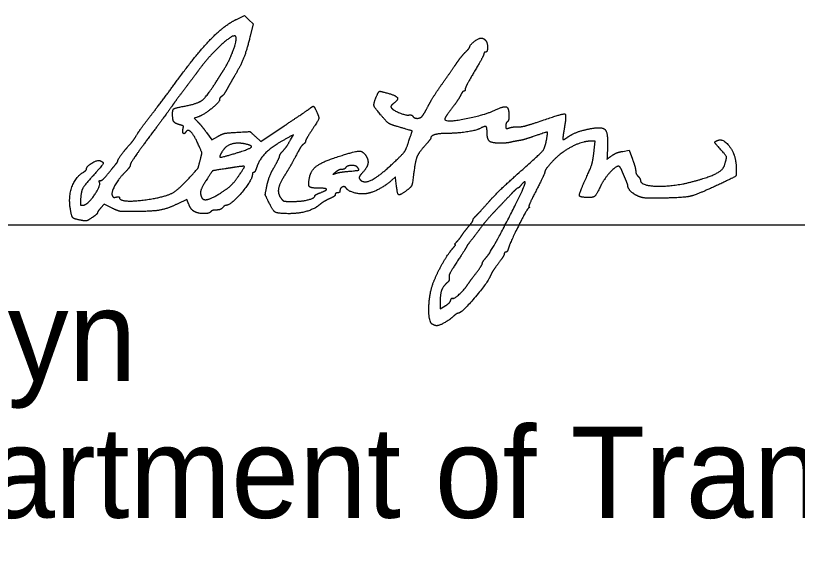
# Model space of a CAD drawing. Extents: x 0 to 44, y -23.8 to 22.
# Drawn here: x 25.658 to 26.858, y 6.74 to 7.554 of the extents above; entities that cross this region are included whole.
import ezdxf

# ---------------------------------------------------------------- set-up
doc = ezdxf.new("R2010")
doc.units = 0
for name, color, linetype in [('Default', 7, 'Continuous'), ('SH_Data', 7, 'Continuous'), ('SH_Text', 7, 'Continuous')]:
    doc.layers.add(name, color=color, linetype=linetype)

msp = doc.modelspace()

# ---------------------------------------------------------------- linework, layer by layer
at = {"layer": 'Default'}
for points in [[(25.9971, 7.5478), (26.0097, 7.5537), (26.0161, 7.5473), (26.0225, 7.5409), (26.0181, 7.5222)], [(25.9372, 7.3978), (25.9322, 7.3963), (25.9373, 7.3911)], [(26.0261, 7.3681), (26.0343, 7.3605), (26.0705, 7.3846)], [(25.951, 7.3744), (25.9595, 7.3629), (25.9683, 7.3681)], [(26.08, 7.3629), (26.0845, 7.3708), (26.079, 7.3679)], [(26.5459, 7.347), (26.5474, 7.3608), (26.5395, 7.3608)], [(26.5897, 7.3453), (26.5994, 7.3469), (26.6045, 7.3333)], [(26.2418, 7.2992), (26.2411, 7.306), (26.2353, 7.3009)], [(25.9242, 7.2636), (25.9208, 7.2716), (25.907, 7.2648)], [(25.8055, 7.2585), (25.794, 7.2643), (25.789, 7.2585)], [(26.3095, 7.1131), (26.3095, 7.1037), (26.3171, 7.108)]]:
    msp.add_lwpolyline(points, dxfattribs=at)
for points in [[(25.9075, 7.4559), (25.9372, 7.4965), (25.979, 7.5394), (25.9971, 7.5478)], [(25.9957, 7.522), (25.992, 7.5257), (25.9535, 7.4899), (25.9381, 7.4686)], [(25.9774, 7.47), (25.9868, 7.4848), (25.9988, 7.5189), (25.9957, 7.522)], [(26.0181, 7.5222), (26.0131, 7.5011), (26.0039, 7.4775), (25.9945, 7.4616)], [(26.3551, 7.5059), (26.3551, 7.5087), (26.3683, 7.519), (26.3721, 7.5191)], [(26.3721, 7.5191), (26.3741, 7.5191), (26.3771, 7.5179), (26.3787, 7.5163)], [(26.3787, 7.5163), (26.3821, 7.5128), (26.3825, 7.4976), (26.3791, 7.4976)], [(26.3348, 7.4806), (26.3387, 7.4864), (26.3449, 7.4941), (26.3485, 7.4978)], [(26.3485, 7.4978), (26.3522, 7.5014), (26.3551, 7.5051), (26.3551, 7.5059)], [(26.3767, 7.495), (26.3767, 7.4937), (26.3703, 7.4816), (26.3623, 7.4682)], [(26.3791, 7.4976), (26.3778, 7.4976), (26.3767, 7.4964), (26.3767, 7.495)], [(26.3131, 7.4496), (26.3211, 7.4608), (26.3308, 7.4747), (26.3348, 7.4806)], [(25.9381, 7.4686), (25.9345, 7.4637), (25.9251, 7.451), (25.9171, 7.4405)], [(25.9668, 7.4533), (25.9701, 7.4585), (25.9748, 7.466), (25.9774, 7.47)], [(25.9945, 7.4616), (25.9909, 7.4556), (25.9857, 7.4464), (25.9829, 7.4412)], [(26.3623, 7.4682), (26.3544, 7.4548), (26.3479, 7.4424), (26.3479, 7.4407)], [(25.8674, 7.4025), (25.8763, 7.4138), (25.8943, 7.4379), (25.9075, 7.4559)], [(25.917, 7.4146), (25.9376, 7.4184), (25.9517, 7.4293), (25.9668, 7.4533)], [(26.2918, 7.416), (26.2956, 7.4232), (26.3052, 7.4383), (26.3131, 7.4496)], [(25.9171, 7.4405), (25.9092, 7.43), (25.9011, 7.419), (25.8991, 7.4161)], [(25.9829, 7.4412), (25.98, 7.4359), (25.9762, 7.4307), (25.9744, 7.4296)], [(26.2111, 7.4278), (26.2148, 7.4369), (26.218, 7.4379), (26.2307, 7.4341)], [(26.3459, 7.4376), (26.3448, 7.4376), (26.3425, 7.4346), (26.3407, 7.431)], [(26.3479, 7.4407), (26.3479, 7.439), (26.347, 7.4376), (26.3459, 7.4376)], [(25.9711, 7.4242), (25.9711, 7.4205), (25.9454, 7.4004), (25.9372, 7.3978)], [(25.9744, 7.4296), (25.9726, 7.4286), (25.9711, 7.4261), (25.9711, 7.4242)], [(26.2209, 7.3984), (26.2094, 7.4114), (26.2071, 7.4182), (26.2111, 7.4278)], [(26.2307, 7.4341), (26.2427, 7.4306), (26.2455, 7.4244), (26.2379, 7.4186)], [(26.3407, 7.431), (26.3389, 7.4273), (26.3328, 7.4182), (26.3271, 7.4108)], [(25.8991, 7.4161), (25.8972, 7.4131), (25.8818, 7.3922), (25.865, 7.3695)], [(25.8991, 7.4025), (25.8991, 7.4094), (25.9033, 7.4121), (25.917, 7.4146)], [(26.0705, 7.3846), (26.0904, 7.3979), (26.108, 7.4098), (26.1096, 7.4111)], [(26.1096, 7.4111), (26.1142, 7.4149), (26.1165, 7.414), (26.1196, 7.4074)], [(26.2379, 7.4186), (26.2351, 7.4165), (26.2336, 7.4136), (26.2346, 7.4123)], [(26.2346, 7.4123), (26.2373, 7.4085), (26.2572, 7.4003), (26.2618, 7.4011)], [(26.2825, 7.3998), (26.2838, 7.4014), (26.2879, 7.4087), (26.2918, 7.416)], [(26.3943, 7.4089), (26.4073, 7.4151), (26.4151, 7.412), (26.4151, 7.4006)], [(25.8458, 7.3731), (25.8488, 7.3779), (25.8585, 7.3911), (25.8674, 7.4025)], [(25.9101, 7.3861), (25.903, 7.3879), (25.8991, 7.3936), (25.8991, 7.4025)], [(26.1196, 7.4074), (26.1239, 7.3978), (26.123, 7.3937), (26.1127, 7.3778)], [(26.2618, 7.4011), (26.2641, 7.4015), (26.2666, 7.4007), (26.2675, 7.3993)], [(26.2675, 7.3993), (26.2696, 7.3958), (26.2797, 7.3961), (26.2825, 7.3998)], [(26.3271, 7.4108), (26.3214, 7.4033), (26.3167, 7.396), (26.3167, 7.3947)], [(26.3167, 7.3947), (26.3167, 7.3894), (26.3764, 7.4004), (26.3943, 7.4089)], [(26.4151, 7.4006), (26.4151, 7.396), (26.4141, 7.3916), (26.4127, 7.3908)], [(26.4575, 7.3898), (26.4978, 7.4037), (26.5038, 7.4021), (26.4996, 7.3782)], [(25.9373, 7.3911), (25.9401, 7.3883), (25.9463, 7.3808), (25.951, 7.3744)], [(26.2443, 7.3832), (26.2336, 7.3864), (26.2287, 7.3895), (26.2209, 7.3984)], [(26.4127, 7.3908), (26.4114, 7.3899), (26.4103, 7.3871), (26.4103, 7.3845)], [(26.4287, 7.3828), (26.4328, 7.3826), (26.4458, 7.3858), (26.4575, 7.3898)], [(25.9152, 7.3798), (25.9161, 7.3834), (25.9149, 7.3849), (25.9101, 7.3861)], [(25.9195, 7.3751), (25.9171, 7.3712), (25.9139, 7.3747), (25.9152, 7.3798)], [(25.9383, 7.3565), (25.9322, 7.3702), (25.9224, 7.3798), (25.9195, 7.3751)], [(25.9976, 7.3746), (26.0179, 7.3757), (26.018, 7.3757), (26.0261, 7.3681)], [(26.1127, 7.3778), (26.1075, 7.3697), (26.1031, 7.3621), (26.1031, 7.361)], [(26.2611, 7.3595), (26.2668, 7.3763), (26.2664, 7.3769), (26.2443, 7.3832)], [(26.3701, 7.3801), (26.3645, 7.3771), (26.3343, 7.3728), (26.3194, 7.3728)], [(26.3815, 7.3754), (26.3815, 7.3827), (26.3779, 7.3843), (26.3701, 7.3801)], [(26.4009, 7.3578), (26.3885, 7.3578), (26.3815, 7.3641), (26.3815, 7.3754)], [(26.4103, 7.3845), (26.4103, 7.3805), (26.4114, 7.38), (26.4157, 7.3814)], [(26.4157, 7.3814), (26.4187, 7.3823), (26.4245, 7.383), (26.4287, 7.3828)], [(26.4728, 7.3632), (26.4749, 7.3747), (26.4731, 7.3751), (26.4521, 7.3679)], [(26.4996, 7.3782), (26.4983, 7.3706), (26.4976, 7.364), (26.498, 7.3635)], [(26.5056, 7.3674), (26.5128, 7.3724), (26.5311, 7.3787), (26.5447, 7.3809)], [(26.5447, 7.3809), (26.5594, 7.3832), (26.567, 7.3728), (26.5663, 7.3515)], [(25.8295, 7.3512), (25.8361, 7.3586), (25.8404, 7.3643), (25.8458, 7.3731)], [(25.865, 7.3695), (25.8482, 7.3469), (25.8344, 7.3267), (25.8343, 7.3248)], [(25.9683, 7.3681), (25.9749, 7.372), (25.9824, 7.3737), (25.9976, 7.3746)], [(26.079, 7.3679), (26.0556, 7.3553), (26.0328, 7.3347), (26.0287, 7.3222)], [(26.0672, 7.3447), (26.0727, 7.3507), (26.0752, 7.3543), (26.08, 7.3629)], [(26.2951, 7.3656), (26.2951, 7.3647), (26.2909, 7.3593), (26.2858, 7.3535)], [(26.3194, 7.3728), (26.3079, 7.3728), (26.2951, 7.369), (26.2951, 7.3656)], [(26.4279, 7.3102), (26.4634, 7.3418), (26.4703, 7.35), (26.4728, 7.3632)], [(26.4521, 7.3679), (26.4443, 7.3652), (26.4347, 7.3624), (26.4307, 7.3618)], [(26.498, 7.3635), (26.4985, 7.363), (26.5019, 7.3648), (26.5056, 7.3674)], [(26.7354, 7.3622), (26.744, 7.3655), (26.7625, 7.3406), (26.7635, 7.3243)], [(25.8151, 7.3308), (25.8151, 7.3324), (25.8243, 7.3454), (25.8295, 7.3512)], [(25.9416, 7.332), (25.9442, 7.3418), (25.9439, 7.344), (25.9383, 7.3565)], [(26.0093, 7.3568), (25.9985, 7.359), (25.9811, 7.3539), (25.9768, 7.3473)], [(25.9987, 7.3433), (26.018, 7.3492), (26.022, 7.3543), (26.0093, 7.3568)], [(26.0996, 7.356), (26.0976, 7.3544), (26.0945, 7.3502), (26.0927, 7.3467)], [(26.1031, 7.361), (26.1031, 7.3599), (26.1015, 7.3576), (26.0996, 7.356)], [(26.2428, 7.3322), (26.2533, 7.3422), (26.2574, 7.3484), (26.2611, 7.3595)], [(26.2858, 7.3535), (26.2773, 7.3441), (26.2716, 7.3315), (26.27, 7.3188)], [(26.4175, 7.3592), (26.4142, 7.3584), (26.4067, 7.3578), (26.4009, 7.3578)], [(26.4307, 7.3618), (26.4268, 7.3611), (26.4208, 7.36), (26.4175, 7.3592)], [(26.5395, 7.3608), (26.5269, 7.3608), (26.4931, 7.3423), (26.4809, 7.3288)], [(26.5663, 7.3515), (26.5656, 7.3331), (26.5654, 7.3334), (26.5732, 7.3389)], [(26.7363, 7.3521), (26.731, 7.3578), (26.7308, 7.3605), (26.7354, 7.3622)], [(26.7455, 7.323), (26.7494, 7.3348), (26.7479, 7.3397), (26.7363, 7.3521)], [(25.9768, 7.3473), (25.9698, 7.3366), (25.9743, 7.3358), (25.9987, 7.3433)], [(26.0633, 7.3377), (26.0635, 7.3395), (26.0653, 7.3426), (26.0672, 7.3447)], [(26.0927, 7.3467), (26.0846, 7.3313), (26.0768, 7.3175), (26.0707, 7.3078)], [(26.1465, 7.335), (26.1784, 7.3456), (26.1918, 7.346), (26.1968, 7.3366)], [(26.5312, 7.2991), (26.5403, 7.319), (26.5443, 7.3322), (26.5459, 7.347)], [(26.5732, 7.3389), (26.577, 7.3416), (26.5844, 7.3445), (26.5897, 7.3453)], [(25.7672, 7.3187), (25.7672, 7.3225), (25.784, 7.3325), (25.7878, 7.331)], [(25.7878, 7.331), (25.7937, 7.3287), (25.7915, 7.3238), (25.7771, 7.3079)], [(25.8127, 7.3265), (25.8141, 7.328), (25.8151, 7.33), (25.8151, 7.3308)], [(25.9219, 7.3015), (25.938, 7.319), (25.9383, 7.3196), (25.9416, 7.332)], [(26.0548, 7.3206), (26.0592, 7.3283), (26.063, 7.336), (26.0633, 7.3377)], [(26.1089, 7.3039), (26.111, 7.3152), (26.1272, 7.3286), (26.1465, 7.335)], [(26.1858, 7.3033), (26.1912, 7.2947), (26.2179, 7.3082), (26.2428, 7.3322)], [(26.1968, 7.3366), (26.2001, 7.3305), (26.1967, 7.3191), (26.1892, 7.3112)], [(26.4809, 7.3288), (26.4751, 7.3223), (26.4703, 7.3157), (26.4703, 7.3142)], [(26.6045, 7.3333), (26.6073, 7.3259), (26.6095, 7.3177), (26.6095, 7.3152)], [(25.7625, 7.3134), (25.765, 7.315), (25.7672, 7.3174), (25.7672, 7.3187)], [(25.8006, 7.3116), (25.806, 7.3182), (25.8114, 7.3249), (25.8127, 7.3265)], [(25.8343, 7.3248), (25.8343, 7.3228), (25.8309, 7.318), (25.827, 7.314)], [(25.9795, 7.3185), (25.9618, 7.3159), (25.9597, 7.3148), (25.9525, 7.3036)], [(25.9969, 7.3212), (25.9913, 7.3203), (25.9835, 7.3191), (25.9795, 7.3185)], [(26.0019, 7.3095), (26.0098, 7.3209), (26.0088, 7.323), (25.9969, 7.3212)], [(26.0287, 7.3222), (26.027, 7.317), (26.0247, 7.3128), (26.0236, 7.3128)], [(26.0439, 7.2928), (26.0455, 7.3005), (26.0504, 7.313), (26.0548, 7.3206)], [(26.1587, 7.3176), (26.1563, 7.3176), (26.1524, 7.3158), (26.1498, 7.3138)], [(26.1642, 7.3197), (26.1634, 7.3185), (26.161, 7.3176), (26.1587, 7.3176)], [(26.1827, 7.3208), (26.1799, 7.3241), (26.1664, 7.3234), (26.1642, 7.3197)], [(26.1667, 7.3144), (26.1835, 7.3159), (26.1859, 7.3169), (26.1827, 7.3208)], [(26.27, 7.3188), (26.2671, 7.2963), (26.2654, 7.2908), (26.2597, 7.2863)], [(26.5828, 7.3224), (26.5784, 7.3224), (26.5602, 7.3018), (26.5555, 7.2917)], [(26.5883, 7.3158), (26.5869, 7.3194), (26.5843, 7.3224), (26.5828, 7.3224)], [(26.5943, 7.3016), (26.5925, 7.3058), (26.5898, 7.3121), (26.5883, 7.3158)], [(26.6095, 7.3152), (26.6095, 7.3127), (26.6112, 7.3091), (26.6131, 7.3071)], [(26.6966, 7.2988), (26.7203, 7.305), (26.7432, 7.3164), (26.7455, 7.323)], [(26.7635, 7.3243), (26.7644, 7.309), (26.7617, 7.3059), (26.7383, 7.2949)], [(25.7423, 7.2571), (25.7393, 7.2756), (25.7501, 7.3057), (25.7625, 7.3134)], [(25.7771, 7.3079), (25.7634, 7.2928), (25.7585, 7.2826), (25.7579, 7.2688)], [(25.7883, 7.3003), (25.7897, 7.2999), (25.7953, 7.305), (25.8006, 7.3116)], [(25.827, 7.314), (25.8171, 7.3044), (25.8047, 7.2823), (25.8065, 7.2776)], [(25.9525, 7.3036), (25.9443, 7.2909), (25.9411, 7.2811), (25.9433, 7.2753)], [(25.9721, 7.2808), (25.9832, 7.2878), (25.9942, 7.2983), (26.0019, 7.3095)], [(26.0215, 7.3098), (26.0214, 7.3012), (25.9883, 7.2624), (25.9811, 7.2624)], [(26.0236, 7.3128), (26.0224, 7.3128), (26.0215, 7.3114), (26.0215, 7.3098)], [(26.0707, 7.3078), (26.0627, 7.2952), (26.0604, 7.28), (26.0655, 7.2732)], [(26.1225, 7.2888), (26.111, 7.2888), (26.1069, 7.2933), (26.1089, 7.3039)], [(26.1498, 7.3138), (26.1452, 7.31), (26.1452, 7.31), (26.1499, 7.3117)], [(26.1499, 7.3117), (26.1526, 7.3126), (26.1601, 7.3138), (26.1667, 7.3144)], [(26.1892, 7.3112), (26.1865, 7.3083), (26.185, 7.3048), (26.1858, 7.3033)], [(26.3839, 7.2675), (26.3911, 7.2759), (26.4109, 7.2951), (26.4279, 7.3102)], [(26.4703, 7.3142), (26.4703, 7.3126), (26.4644, 7.2998), (26.4571, 7.2856)], [(26.6131, 7.3071), (26.6151, 7.3051), (26.6167, 7.3024), (26.6167, 7.3011)], [(25.7627, 7.2628), (25.769, 7.2637), (25.7891, 7.2922), (25.7871, 7.2974)], [(25.7871, 7.2974), (25.7864, 7.2993), (25.7869, 7.3006), (25.7883, 7.3003)], [(25.8654, 7.2721), (25.8882, 7.2758), (25.9078, 7.286), (25.9219, 7.3015)], [(26.0459, 7.2688), (26.0414, 7.2779), (26.0412, 7.2801), (26.0439, 7.2928)], [(26.1654, 7.2889), (26.1634, 7.2922), (26.1559, 7.289), (26.1559, 7.2849)], [(26.2353, 7.3009), (26.2259, 7.2927), (26.2059, 7.2821), (26.1967, 7.2804)], [(26.2597, 7.2863), (26.248, 7.2771), (26.2436, 7.2802), (26.2418, 7.2992)], [(26.3813, 7.1837), (26.3889, 7.1924), (26.4421, 7.2962), (26.44, 7.2982)], [(26.4343, 7.2942), (26.4319, 7.2912), (26.4293, 7.2888), (26.4286, 7.2888)], [(26.44, 7.2982), (26.4393, 7.299), (26.4368, 7.2971), (26.4343, 7.2942)], [(26.5386, 7.2744), (26.524, 7.2744), (26.5224, 7.2798), (26.5312, 7.2991)], [(26.5555, 7.2917), (26.5497, 7.2793), (26.5449, 7.2744), (26.5386, 7.2744)], [(26.5976, 7.292), (26.5976, 7.2931), (26.5961, 7.2974), (26.5943, 7.3016)], [(26.6133, 7.2764), (26.6062, 7.2798), (26.5978, 7.2882), (26.5976, 7.292)], [(26.6167, 7.3011), (26.6167, 7.2926), (26.6673, 7.2911), (26.6966, 7.2988)], [(26.7383, 7.2949), (26.7035, 7.2786), (26.6825, 7.2738), (26.6431, 7.2734)], [(25.9433, 7.2753), (25.9453, 7.27), (25.9589, 7.2727), (25.9721, 7.2808)], [(26.1175, 7.277), (26.1175, 7.278), (26.1213, 7.2802), (26.1258, 7.2818)], [(26.1258, 7.2818), (26.1361, 7.2856), (26.1346, 7.2888), (26.1225, 7.2888)], [(26.1487, 7.2791), (26.1487, 7.2777), (26.1463, 7.2755), (26.1433, 7.2742)], [(26.1523, 7.2816), (26.1504, 7.2816), (26.1487, 7.2804), (26.1487, 7.2791)], [(26.1559, 7.2849), (26.1559, 7.2831), (26.1543, 7.2816), (26.1523, 7.2816)], [(26.1967, 7.2804), (26.1881, 7.2789), (26.1683, 7.2842), (26.1654, 7.2889)], [(26.4198, 7.281), (26.4157, 7.2767), (26.4052, 7.2656), (26.3963, 7.2563)], [(26.4286, 7.2888), (26.4278, 7.2888), (26.4238, 7.2852), (26.4198, 7.281)], [(26.4571, 7.2856), (26.4498, 7.2715), (26.4447, 7.2599), (26.4457, 7.2599)], [(25.7579, 7.2688), (25.7576, 7.2632), (25.7584, 7.2622), (25.7627, 7.2628)], [(25.8065, 7.2776), (25.8075, 7.2752), (25.8098, 7.2743), (25.8128, 7.2751)], [(25.8128, 7.2751), (25.8154, 7.2757), (25.8175, 7.2754), (25.8175, 7.2743)], [(25.8175, 7.2743), (25.8175, 7.2697), (25.8432, 7.2685), (25.8654, 7.2721)], [(26.0776, 7.2496), (26.0601, 7.2497), (26.0531, 7.254), (26.0459, 7.2688)], [(26.0655, 7.2732), (26.0684, 7.2694), (26.072, 7.2684), (26.0831, 7.2684)], [(26.0831, 7.2684), (26.0971, 7.2684), (26.1175, 7.2735), (26.1175, 7.277)], [(26.1433, 7.2742), (26.136, 7.2709), (26.1284, 7.2664), (26.1241, 7.2629)], [(26.3654, 7.2471), (26.3683, 7.2499), (26.3766, 7.2591), (26.3839, 7.2675)], [(26.6431, 7.2734), (26.6282, 7.2732), (26.6179, 7.2743), (26.6133, 7.2764)], [(25.7589, 7.2394), (25.748, 7.2414), (25.7441, 7.2455), (25.7423, 7.2571)], [(25.789, 7.2585), (25.7862, 7.2553), (25.7839, 7.2519), (25.7839, 7.2509)], [(25.8363, 7.2528), (25.8207, 7.2528), (25.8148, 7.2539), (25.8055, 7.2585)], [(25.907, 7.2648), (25.8914, 7.257), (25.8662, 7.2528), (25.8363, 7.2528)], [(25.9324, 7.2529), (25.9297, 7.2544), (25.926, 7.2592), (25.9242, 7.2636)], [(25.9662, 7.2552), (25.9625, 7.2552), (25.9588, 7.2541), (25.9579, 7.2528)], [(25.9759, 7.2588), (25.9743, 7.2568), (25.9699, 7.2552), (25.9662, 7.2552)], [(25.9811, 7.2624), (25.9799, 7.2624), (25.9776, 7.2607), (25.9759, 7.2588)], [(26.1241, 7.2629), (26.1165, 7.2565), (26.0921, 7.2496), (26.0776, 7.2496)], [(26.3963, 7.2563), (26.3875, 7.247), (26.3776, 7.2358), (26.3743, 7.2313)], [(26.445, 7.2581), (26.4423, 7.2563), (26.417, 7.2053), (26.4141, 7.1958)], [(26.4457, 7.2599), (26.4467, 7.2599), (26.4464, 7.2591), (26.445, 7.2581)], [(25.7756, 7.2435), (25.769, 7.239), (25.7654, 7.2381), (25.7589, 7.2394)], [(25.7839, 7.2509), (25.7839, 7.25), (25.7802, 7.2466), (25.7756, 7.2435)], [(25.9579, 7.2528), (25.956, 7.2496), (25.9385, 7.2497), (25.9324, 7.2529)], [(26.36, 7.2399), (26.36, 7.241), (26.3624, 7.2443), (26.3654, 7.2471)], [(26.3743, 7.2313), (26.3663, 7.2204), (26.3557, 7.2066), (26.3528, 7.2031)], [(26.3533, 7.2301), (26.357, 7.2343), (26.36, 7.2387), (26.36, 7.2399)], [(26.3431, 7.2167), (26.3451, 7.2198), (26.3497, 7.2258), (26.3533, 7.2301)], [(26.3353, 7.2068), (26.3376, 7.2092), (26.3412, 7.2137), (26.3431, 7.2167)], [(26.2994, 7.1444), (26.3052, 7.1592), (26.3224, 7.1891), (26.3295, 7.197)], [(26.3295, 7.197), (26.3322, 7.1999), (26.3336, 7.2024), (26.3328, 7.2024)], [(26.3328, 7.2024), (26.3319, 7.2024), (26.333, 7.2043), (26.3353, 7.2068)], [(26.3503, 7.1992), (26.3503, 7.1986), (26.344, 7.1887), (26.3363, 7.1771)], [(26.3528, 7.2031), (26.3514, 7.2015), (26.3503, 7.1997), (26.3503, 7.1992)], [(26.4141, 7.1958), (26.4132, 7.1928), (26.4114, 7.1904), (26.4102, 7.1904)], [(26.3743, 7.1734), (26.3743, 7.1747), (26.3774, 7.1793), (26.3813, 7.1837)], [(26.4079, 7.1879), (26.4079, 7.1865), (26.4037, 7.1797), (26.3985, 7.1728)], [(26.4102, 7.1904), (26.4089, 7.1904), (26.4079, 7.1892), (26.4079, 7.1879)], [(26.3363, 7.1771), (26.3276, 7.164), (26.3226, 7.1543), (26.3233, 7.1516)], [(26.3641, 7.1575), (26.3697, 7.1649), (26.3743, 7.172), (26.3743, 7.1734)], [(26.3985, 7.1728), (26.3933, 7.1659), (26.3881, 7.1579), (26.3871, 7.1551)], [(26.3233, 7.1516), (26.324, 7.149), (26.3225, 7.1454), (26.3197, 7.143)], [(26.3871, 7.1551), (26.3834, 7.1452), (26.3423, 7.0968), (26.3376, 7.0968)], [(26.3515, 7.1403), (26.3529, 7.1424), (26.3585, 7.1502), (26.3641, 7.1575)], [(26.2975, 7.0799), (26.2916, 7.0837), (26.2929, 7.128), (26.2994, 7.1444)], [(26.3197, 7.143), (26.3137, 7.1377), (26.3095, 7.1254), (26.3095, 7.1131)], [(26.3287, 7.1196), (26.3307, 7.1184), (26.3473, 7.1335), (26.3515, 7.1403)], [(26.3171, 7.108), (26.3212, 7.1104), (26.3251, 7.1142), (26.3257, 7.1165)], [(26.3257, 7.1165), (26.3264, 7.1188), (26.3277, 7.1202), (26.3287, 7.1196)], [(26.3301, 7.0922), (26.3239, 7.0865), (26.308, 7.0775), (26.3041, 7.0776)], [(26.3376, 7.0968), (26.3362, 7.0968), (26.3328, 7.0947), (26.3301, 7.0922)], [(26.3041, 7.0776), (26.3025, 7.0776), (26.2995, 7.0787), (26.2975, 7.0799)]]:
    msp.add_open_spline(points, degree=2, dxfattribs=at)
at = {"layer": 'SH_Data'}
msp.add_line((24.5118, 7.2326), (28.0118, 7.2326), dxfattribs=at)

# ---------------------------------------------------------------- texts
at = {"layer": 'SH_Text'}
for s, p in [('Pamela Boratyn', (24.5118, 6.9926)), ('Director, Department of Transportation', (24.5118, 6.7826))]:
    msp.add_text(s, height=0.14, dxfattribs=at).set_placement(p)

doc.saveas('drawing.dxf')
